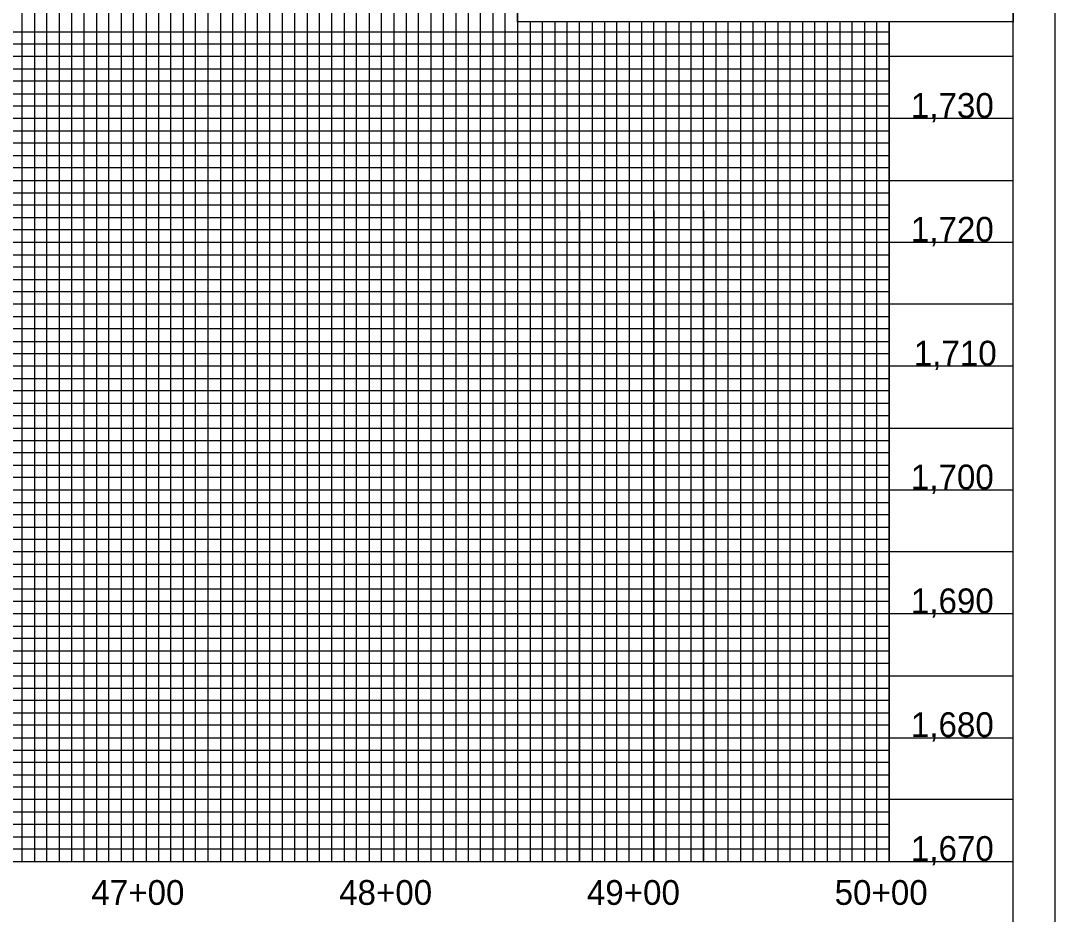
# Model space of a CAD drawing. Extents: x 505602 to 507286, y 483109 to 484209.
# Drawn here: x 506868.5 to 507286.1, y 483662.4 to 484023.2 of the extents above; entities that cross this region are included whole.
import ezdxf

# ---------------------------------------------------------------- set-up
doc = ezdxf.new("R2010")
doc.units = 0
for name, color, linetype in [('Exist Vertical Profile Vertical Axis Label', 7, 'Continuous'), ('Sheet Layout Profile Border Port 1', 7, 'Continuous'), ('Sheet Plot Border Outside CELL', 7, 'Continuous'), ('Sheet Profile CELL', 7, 'Continuous'), ('Sheet Profile Grid Major CELL', 7, 'Continuous'), ('Sheet Profile Grid Middle CELL', 7, 'Continuous'), ('Sheet Profile Grid Minor CELL', 7, 'Continuous'), ('Sheet Sticker Exception Certification CELL', 7, 'Continuous')]:
    doc.layers.add(name, color=color, linetype=linetype)

msp = doc.modelspace()

# ---------------------------------------------------------------- linework, layer by layer
at = {"layer": 'Sheet Layout Profile Border Port 1'}
msp.add_lwpolyline([(505819.08, 484183.71), (505819.08, 483683.71), (507219.08, 483683.71), (507219.08, 484022.66), (507069.03, 484022.66), (507069.03, 484183.71)], close=True, dxfattribs=at)
at = {"layer": 'Sheet Plot Border Outside CELL'}
msp.add_lwpolyline([(505602.08, 483108.71), (507286.08, 483108.71), (507286.08, 484208.71), (505602.08, 484208.71)], close=True, dxfattribs=at)
at = {"layer": 'Sheet Profile CELL'}
msp.add_line((505769.08, 483683.71), (507269.08, 483683.71), dxfattribs=at)
msp.add_lwpolyline([(507269.08, 484183.71), (505769.08, 484183.71), (505769.08, 483133.71), (507269.08, 483133.71)], close=True, dxfattribs=at)
at = {"layer": 'Sheet Profile Grid Major CELL'}
for points in [[(506819.08, 483683.71), (506869.08, 483683.71), (506869.08, 484183.71), (506919.08, 484183.71), (506919.08, 483683.71), (506969.08, 483683.71), (506969.08, 484183.71), (507019.08, 484183.71), (507019.08, 483683.71), (507069.08, 483683.71), (507069.08, 484183.71), (507095.38, 484183.71)], [(507219.08, 484022.66), (507219.08, 483683.71), (507269.08, 483683.71), (507269.08, 484033.71)], [(507119.08, 484022.66), (507119.08, 483683.71), (507169.08, 483683.71), (507169.08, 483683.71), (507169.08, 484022.66)], [(507269.08, 483983.71), (505769.08, 483983.71), (505769.08, 483933.71), (507269.08, 483933.71)], [(507269.08, 483883.71), (505769.08, 483883.71), (505769.08, 483833.71), (507269.08, 483833.71)], [(507269.08, 483783.71), (505769.08, 483783.71), (505769.08, 483783.71), (505769.08, 483733.71), (507269.08, 483733.71)]]:
    msp.add_lwpolyline(points, dxfattribs=at)
at = {"layer": 'Sheet Profile Grid Middle CELL'}
for points in [[(506844.08, 483683.71), (506894.08, 483683.71), (506894.08, 484183.71), (506944.08, 484183.71), (506944.08, 483683.71), (506994.08, 483683.71), (506994.08, 484183.71), (507044.08, 484183.71), (507044.08, 483683.71), (507094.08, 483683.71), (507094.08, 484022.66)], [(507094.08, 483946.51), (507094.08, 483683.71), (507144.08, 483683.71), (507144.08, 484022.66)], [(507144.08, 483946.51), (507144.08, 483683.71), (507194.08, 483683.71), (507194.08, 484022.66)], [(507269.08, 484008.71), (505769.08, 484008.71), (505769.08, 483958.71), (507094.08, 483958.71)], [(507094.08, 483958.71), (507269.08, 483958.71)], [(507269.08, 483908.71), (505769.08, 483908.71), (505769.08, 483858.71), (507269.08, 483858.71)], [(507269.08, 483808.71), (505769.08, 483808.71), (505769.08, 483758.71), (507269.08, 483758.71)], [(507269.08, 483708.71), (505769.08, 483708.71)]]:
    msp.add_lwpolyline(points, dxfattribs=at)
at = {"layer": 'Sheet Profile Grid Minor CELL'}
for p, q in [((505819.08, 484018.71), (507219.08, 484018.71)), ((507219.08, 483998.71), (505819.08, 483998.71)), ((505819.08, 483993.71), (507219.08, 483993.71)), ((507219.08, 483973.71), (505819.08, 483973.71)), ((505819.08, 483968.71), (507219.08, 483968.71)), ((507219.08, 483948.71), (505819.08, 483948.71)), ((505819.08, 483943.71), (507219.08, 483943.71)), ((507219.08, 483938.71), (505819.08, 483938.71)), ((505819.08, 483928.71), (507219.08, 483928.71)), ((507219.08, 483923.71), (505819.08, 483923.71)), ((505819.08, 483918.71), (507219.08, 483918.71)), ((507219.08, 483913.71), (505819.08, 483913.71)), ((505819.08, 483903.71), (507219.08, 483903.71)), ((507219.08, 483898.71), (505819.08, 483898.71)), ((505819.08, 483893.71), (507219.08, 483893.71)), ((507219.08, 483888.71), (505819.08, 483888.71)), ((505819.08, 483878.71), (507219.08, 483878.71)), ((507219.08, 483873.71), (505819.08, 483873.71)), ((505819.08, 483868.71), (507219.08, 483868.71)), ((507219.08, 483863.71), (505819.08, 483863.71)), ((505819.08, 483853.71), (507219.08, 483853.71)), ((507219.08, 483848.71), (505819.08, 483848.71)), ((505819.08, 483843.71), (507219.08, 483843.71)), ((507219.08, 483838.71), (505819.08, 483838.71)), ((505819.08, 483828.71), (507219.08, 483828.71)), ((507219.08, 483823.71), (505819.08, 483823.71)), ((505819.08, 483818.71), (507219.08, 483818.71)), ((507219.08, 483813.71), (505819.08, 483813.71)), ((505819.08, 483803.71), (507219.08, 483803.71)), ((507219.08, 483798.71), (505819.08, 483798.71)), ((507219.08, 483793.71), (505819.08, 483793.71)), ((507219.08, 483788.71), (505819.08, 483788.71)), ((505819.08, 483778.71), (507219.08, 483778.71)), ((507219.08, 483773.71), (505819.08, 483773.71)), ((505819.08, 483768.71), (507219.08, 483768.71)), ((507219.08, 483763.71), (505819.08, 483763.71)), ((505819.08, 483753.71), (507219.08, 483753.71)), ((507219.08, 483748.71), (505819.08, 483748.71)), ((505819.08, 483743.71), (507219.08, 483743.71)), ((507219.08, 483738.71), (505819.08, 483738.71)), ((505819.08, 483728.71), (507219.08, 483728.71)), ((507219.08, 483723.71), (505819.08, 483723.71)), ((505819.08, 483718.71), (507219.08, 483718.71)), ((507219.08, 483713.71), (505819.08, 483713.71)), ((505819.08, 483703.71), (507219.08, 483703.71)), ((507219.08, 483698.71), (505819.08, 483698.71)), ((505819.08, 483693.71), (507219.08, 483693.71))]:
    msp.add_line(p, q, dxfattribs=at)
for points in [[(506874.08, 484183.71), (506874.08, 483683.71), (506879.08, 483683.71), (506879.08, 484183.71)], [(506884.08, 484183.71), (506884.08, 483683.71), (506889.08, 483683.71), (506889.08, 484183.71)], [(506899.08, 484183.71), (506899.08, 483683.71), (506904.08, 483683.71), (506904.08, 484183.71)], [(506909.08, 484183.71), (506909.08, 483683.71), (506914.08, 483683.71), (506914.08, 484183.71)], [(506924.08, 484183.71), (506924.08, 483683.71), (506929.08, 483683.71), (506929.08, 484183.71)], [(506934.08, 484183.71), (506934.08, 483683.71), (506939.08, 483683.71), (506939.08, 484183.71)], [(506949.08, 484183.71), (506949.08, 483683.71), (506954.08, 483683.71), (506954.08, 484183.71)], [(506959.08, 484183.71), (506959.08, 483683.71)], [(506959.08, 483683.71), (506964.08, 483683.71), (506964.08, 484183.71)], [(506974.08, 484183.71), (506974.08, 483683.71), (506979.08, 483683.71), (506979.08, 484183.71)], [(506984.08, 484183.71), (506984.08, 483683.71), (506989.08, 483683.71), (506989.08, 484183.71)], [(506999.08, 484183.71), (506999.08, 483683.71), (507004.08, 483683.71), (507004.08, 484183.71)], [(507009.08, 484183.71), (507009.08, 483683.71), (507014.08, 483683.71), (507014.08, 484183.71)], [(507024.08, 484183.71), (507024.08, 483683.71), (507029.08, 483683.71), (507029.08, 484183.71)], [(507034.08, 484183.71), (507034.08, 483683.71), (507039.08, 483683.71), (507039.08, 484183.71)], [(507049.08, 484183.71), (507049.08, 483683.71), (507054.08, 483683.71), (507054.08, 484183.71)], [(507059.08, 484183.71), (507059.08, 483683.71), (507064.08, 483683.71), (507064.08, 484183.71)], [(507074.08, 484022.66), (507074.08, 483683.71), (507079.08, 483683.71), (507079.08, 484022.66)], [(507084.08, 484022.66), (507084.08, 483683.71), (507089.08, 483683.71), (507089.08, 484022.66)], [(507099.08, 484022.66), (507099.08, 483683.71), (507099.08, 483683.71), (507104.08, 483683.71), (507109.08, 483683.71), (507109.08, 484022.66)], [(507104.08, 484022.66), (507104.08, 483683.71)], [(507114.07, 484022.66), (507113.98, 483683.76), (507118.98, 483683.76), (507124.08, 483683.71), (507124.08, 484022.66)], [(507124.08, 483946.51), (507124.08, 483683.71), (507129.08, 483683.71), (507129.08, 484022.66)], [(507134.08, 484022.66), (507134.08, 483683.71), (507139.08, 483683.71), (507139.08, 484022.66)], [(507149.08, 484022.66), (507149.08, 483683.71), (507154.08, 483683.71), (507154.08, 484022.66)], [(507159.08, 484022.66), (507159.08, 483683.71), (507164.08, 483683.71), (507164.08, 484022.66)], [(507174.08, 484022.66), (507174.08, 483683.71), (507179.08, 483683.71), (507179.08, 484022.66)], [(507184.08, 484022.66), (507184.08, 483683.71), (507189.08, 483683.71), (507189.08, 484022.66)], [(507199.08, 484022.66), (507199.08, 483683.71), (507204.08, 483683.71), (507204.08, 484022.66)], [(507209.08, 484022.66), (507209.08, 483683.71), (507214.08, 483683.71), (507214.08, 484022.66)], [(507219.08, 484013.71), (505819.08, 484013.71), (505819.08, 484003.71), (507219.08, 484003.71)], [(507219.08, 483988.71), (505819.08, 483988.71), (505819.08, 483978.71), (507219.08, 483978.71)], [(507219.08, 483963.71), (505819.08, 483963.71), (505819.08, 483953.71), (507219.08, 483953.71)], [(507219.08, 483688.71), (505819.08, 483688.71)]]:
    msp.add_lwpolyline(points, dxfattribs=at)
at = {"layer": 'Sheet Sticker Exception Certification CELL'}
for p, q in [((507069.03, 484022.66), (507069.03, 484046.16)), ((507069.03, 484022.66), (507069.03, 484046.16)), ((507269.07, 484046.15), (507269.07, 484022.65)), ((507269.07, 484046.15), (507269.07, 484022.65)), ((507269.07, 484022.66), (507069.03, 484022.66)), ((507269.07, 484022.66), (507069.03, 484022.66))]:
    msp.add_line(p, q, dxfattribs=at)

# ---------------------------------------------------------------- texts
at = {"layer": 'Exist Vertical Profile Vertical Axis Label'}
for s, p in [('1,730', (507227.78, 483983.96)), ('1,720', (507227.78, 483933.96)), ('1,710', (507228.97, 483883.96)), ('1,700', (507227.78, 483833.96)), ('1,690', (507227.78, 483783.96)), ('1,680', (507227.78, 483733.96)), ('1,670', (507227.78, 483683.96)), ('47+00', (506897.01, 483666.21)), ('48+00', (506997.01, 483666.21)), ('49+00', (507097.01, 483666.21)), ('50+00', (507197.01, 483666.21))]:
    msp.add_text(s, height=10, dxfattribs=at).set_placement(p)

doc.saveas('drawing.dxf')
